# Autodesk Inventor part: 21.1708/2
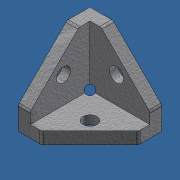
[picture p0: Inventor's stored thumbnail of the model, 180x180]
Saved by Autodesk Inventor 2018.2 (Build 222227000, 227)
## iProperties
Created: 2007-01
Part Number: 21.1708/2
Document SubType Name: Modeling
Designer: Andy Moles
Material: Aluminum-6061
Density: 2.71 g/cm^3
Stock Number: Angle 45 Deg Al Casting
Appearance: Aluminum Cast
Author: Andy Moles
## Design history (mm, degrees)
sketch "Sketch1"
  geometry: L1 (0, 0)-(0, -42); L2 (0, 0)-(42, 0); L3 (0, -42)-(13.5, -42); L4 (42, 0)-(42, -13.5); L5 (13.5, -42)-(42, -13.5)
  constraints: 10 end point, 2 perpendicular, 1 parallel, 1 vertical
  dimensions: "d0" = 42 distance of L1.start L1.end; "d1" = 42 distance of L1.start L2.end; "d2" = 13.5 distance of L1.end L3.end; "d3" = 13.5 distance of L2.end L4.end (= d2)
extrude "Extrusion1" new body sketch "Sketch1" distance "d4" = 42; taper "d5" = 0 deg
sketch "Sketch2"
  geometry: L1 (0, 0)-(42, 0) reference; L2 (0, -42)-(0, 0) reference; L3 (7, -7)-(57.245, -7); L4 (57.245, -7)-(57.245, -50.91); L5 (57.245, -50.91)-(7, -50.91); L6 (7, -50.91)-(7, -7)
  constraints: 8 end point, 2 parallel, 1 horizontal, 1 perpendicular
  dimensions: "d6" = 7 distance between parallel lines of L3 L1; "d7" = 7 distance between parallel lines of L6 L2
extrude "Extrusion2" cut sketch "Sketch2" distance "d8" = 35; taper "d9" = 0 deg
sketch "Sketch3"
  geometry: L1 (42, 0)-(42, 42) reference; L2 (0, 42)-(42, 42) reference; L3 (0, 0)-(42, 0) reference; L4 (42, 28.5)-(13.5, 0); L5 (13.5, 0)-(42, 0); L6 (42, 0)-(42, 28.5)
  constraints: 6 end point, 2 collinear, 2 point on line
  dimensions: "d10" = 13.5 distance from line of L4.start L2; "d11" = 13.5 distance of L3.start L4.end (= d10)
extrude "Extrusion3" cut sketch "Sketch3" extent not by distance; stored distance "d12" = 35; taper "d13" = 0 deg
sketch "Sketch4"
  geometry: L1 (0, -42)-(42, -42) reference; L2 (42, 0)-(42, -42) reference; L3 (42, 0)-(0, 0) reference; L4 (13.5, -42)-(42, -13.5); L5 (42, -13.5)-(42, -42); L6 (42, -42)-(13.5, -42)
  constraints: 6 end point, 2 collinear, 2 point on line
  dimensions: "d14" = 13.5 distance from line of L4.end L3 (= d15); "d15" = 13.5 distance of L1.start L4.start
extrude "Extrusion4" cut sketch "Sketch4" distance "d16" = 35; taper "d17" = 0 deg
hole "Hole1" diameter "d20" = 8.2; stored, may be unused: countersink angle "d24" = 90 deg, drill point angle "d26" = 118 deg; dims "d18" = 22.5, "d19" = 22.5, "d21" = 6, "d22" = 4, "d23" = 2, "d25" = 8
hole "Hole2" diameter "d29" = 8.2; stored, may be unused: countersink angle "d33" = 90 deg, drill point angle "d35" = 118 deg; dims "d27" = 22.5, "d28" = 22.5, "d30" = 6, "d31" = 4, "d32" = 2, "d34" = 8
hole "Hole3" diameter "d38" = 8.2; stored, may be unused: countersink angle "d42" = 90 deg, drill point angle "d44" = 118 deg; dims "d36" = 22.5, "d37" = 22.5, "d39" = 6, "d40" = 4, "d41" = 2, "d43" = 8
sketch "Sketch5"
  geometry: L1 (29.25, 29.5)-(29.25, 19.5); L2 (15.75, 29.5)-(15.75, 19.5); C1 r 4.1 at (22.5, 19.5) reference; A1 r 6.75 centre (22.5, 19.5) between (15.75, 19.5) and (29.25, 19.5); A2 r 6.75 centre (22.5, 29.5) between (29.25, 29.5) and (15.75, 29.5)
  constraints: 4 end point, 4 point on circle, 4 tangent, 2 centre point, 1 coincident, 1 vertical alignment
  dimensions: "d45" = 13.5 diameter of A1; "d46" = 13.5 diameter of A2; "d47" = 23.5 dimension on A1 A2
extrude "Extrusion5" cut sketch "Sketch5" distance "d48" = 2; taper "d49" = 0 deg
sketch "Sketch6"
  geometry: L1 (29.25, -12.5)-(29.25, -22.5); L2 (15.75, -12.5)-(15.75, -22.5); C1 r 4.1 at (22.5, -22.5) reference; A1 r 6.75 centre (22.5, -22.5) between (15.75, -22.5) and (29.25, -22.5); A2 r 6.75 centre (22.5, -12.5) between (29.25, -12.5) and (15.75, -12.5)
  constraints: 4 end point, 4 point on circle, 3 tangent, 2 centre point, 1 coincident, 1 parallel, 1 vertical alignment
  dimensions: "d50" = 13.5 diameter of A1; "d51" = 13.5 diameter of A2; "d52" = 23.5 dimension on A1 A2
extrude "Extrusion6" cut sketch "Sketch6" distance "d53" = 2; taper "d54" = 0 deg
sketch "Sketch7"
  geometry: L1 (0, -42)-(-13.5, -42) reference; L2 (-22.5, -22.5)-(-29.25, -22.5); L3 (-22.5, -22.5)-(-5.75, -22.5); L4 (-22.516, -15.75)-(-12.516, -15.727); L5 (-12.484, -29.227)-(-22.484, -29.25); C1 r 4.1 at (-22.5, -22.5) reference; A1 r 6.75 centre (-22.5, -22.5) between (-22.516, -15.75) and (-22.484, -29.25); A2 r 6.75 centre (-12.5, -22.477) between (-12.484, -29.227) and (-12.516, -15.727)
  constraints: 8 end point, 6 point on circle, 3 tangent, 2 centre point, 2 parallel, 1 coincident, 1 collinear
  dimensions: "d55" = 13.5 diameter of A1; "d56" = 13.5 diameter of A2; "d57" = 23.5 distance of L3.end L2.end
extrude "Extrusion7" cut sketch "Sketch7" distance "d58" = 2; taper "d59" = 0 deg
workplane "Work Plane1"
sketch "Sketch8"
  geometry: L1 (29.698, 17.146)-(4.95, 2.858) reference; L2 (54.447, 2.858)-(29.698, 17.146) reference; L3 (29.698, 45.724)-(29.698, 17.146) reference; C1 r 2.45 at (29.698, 17.146)
  constraints: 1 centre point, 1 coincident
  dimensions: "d60" = 4.9 diameter of C1
extrude "Extrusion8" cut sketch "Sketch8" extent not by distance; stored distance "d61" = 10; taper "d62" = 0 deg
fillet "Fillet1" dims "d63" = 2
body "Solid1"
